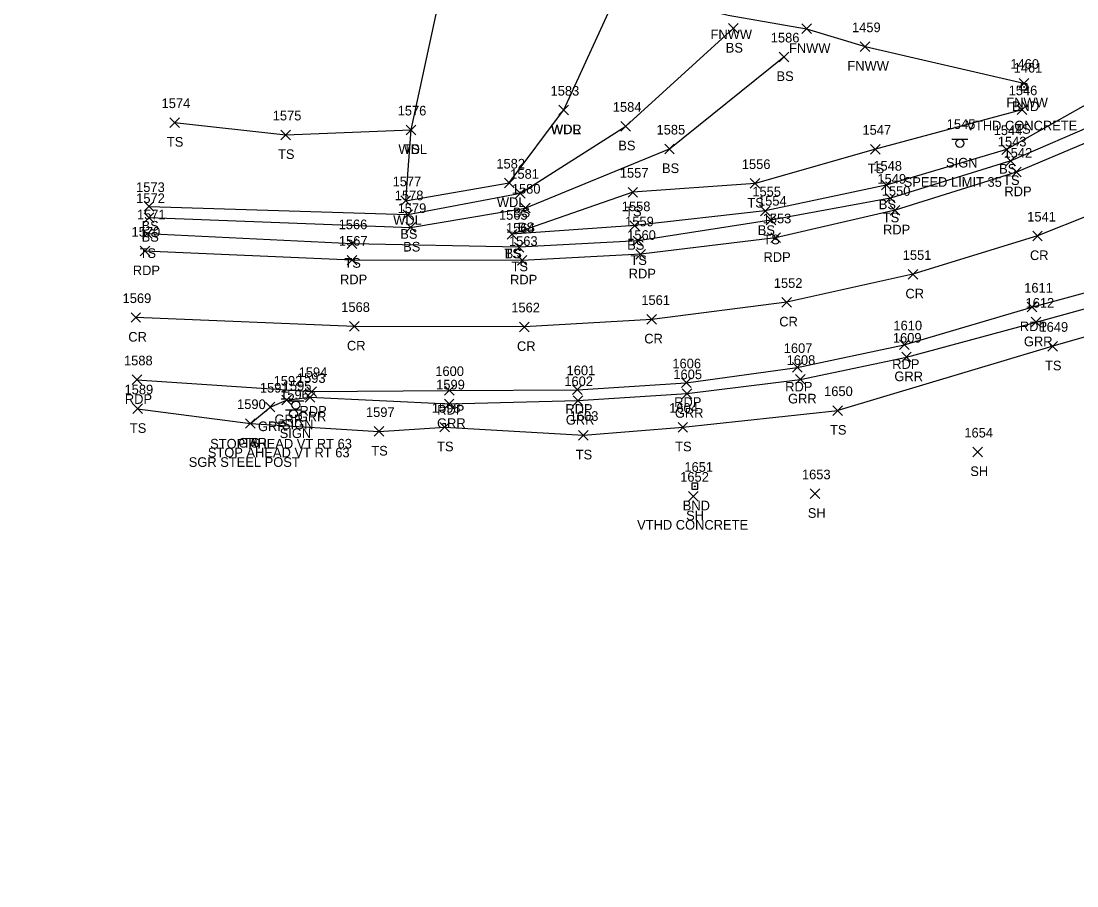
# Model space of a CAD drawing. Extents: x 1629176 to 1637209, y 606063 to 610167.
# Drawn here: x 1629563.1 to 1629782.2, y 606671.7 to 606851.1 of the extents above; entities that cross this region are included whole.
import ezdxf

# ---------------------------------------------------------------- set-up
doc = ezdxf.new("R2010")
doc.units = 0
for name, color, linetype in [('L_A', 7, 'Continuous'), ('L_C', 7, 'Continuous'), ('L_I', 7, 'Continuous'), ('L_TIC', 7, 'Continuous'), ('LAWA', 7, 'Continuous'), ('LELB', 7, 'Continuous'), ('LFNC', 7, 'Continuous'), ('M_A', 7, 'Continuous'), ('M_C', 7, 'Continuous'), ('M_I', 7, 'Continuous'), ('MHBP', 7, 'Continuous'), ('P_A', 7, 'Continuous'), ('P_I', 7, 'Continuous'), ('P_TIC', 7, 'Continuous'), ('PET', 7, 'Continuous'), ('PRC', 7, 'Continuous'), ('R_A', 7, 'Continuous'), ('R_C', 7, 'Continuous'), ('R_I', 7, 'Continuous'), ('R_TIC', 7, 'Continuous'), ('RGR', 7, 'Continuous'), ('S_A', 7, 'Continuous'), ('S_C', 7, 'Continuous'), ('S_I', 7, 'Continuous'), ('SSGN', 7, 'Continuous')]:
    doc.layers.add(name, color=color, linetype=linetype)

msp = doc.modelspace()

# ---------------------------------------------------------------- linework, layer by layer
at = {"layer": 'L_TIC'}
for points in [[(1629709.9, 606848.62), (1629711.9, 606850.62)], [(1629711.9, 606848.62), (1629709.9, 606850.62)], [(1629725.11, 606848.55), (1629727.11, 606850.55)], [(1629727.11, 606848.55), (1629725.11, 606850.55)], [(1629737.25, 606844.85), (1629739.25, 606846.85)], [(1629739.25, 606844.85), (1629737.25, 606846.85)], [(1629720.42, 606842.72), (1629722.42, 606844.72)], [(1629722.42, 606842.72), (1629720.42, 606844.72)], [(1629770.23, 606837.25), (1629772.23, 606839.25)], [(1629772.23, 606837.25), (1629770.23, 606839.25)], [(1629674.67, 606831.68), (1629676.67, 606833.68)], [(1629676.67, 606831.68), (1629674.67, 606833.68)], [(1629674.67, 606831.68), (1629676.67, 606833.68)], [(1629676.67, 606831.68), (1629674.67, 606833.68)], [(1629769.8, 606831.77), (1629771.8, 606833.77)], [(1629771.8, 606831.77), (1629769.8, 606833.77)], [(1629593.93, 606829.1), (1629595.93, 606831.1)], [(1629595.93, 606829.1), (1629593.93, 606831.1)], [(1629617, 606826.54), (1629619, 606828.54)], [(1629619, 606826.54), (1629617, 606828.54)], [(1629642.99, 606827.57), (1629644.99, 606829.57)], [(1629644.99, 606827.57), (1629642.99, 606829.57)], [(1629642.99, 606827.57), (1629644.99, 606829.57)], [(1629644.99, 606827.57), (1629642.99, 606829.57)], [(1629687.59, 606828.33), (1629689.59, 606830.33)], [(1629689.59, 606828.33), (1629687.59, 606830.33)], [(1629696.66, 606823.62), (1629698.66, 606825.62)], [(1629698.66, 606823.62), (1629696.66, 606825.62)], [(1629739.4, 606823.57), (1629741.4, 606825.57)], [(1629741.4, 606823.57), (1629739.4, 606825.57)], [(1629766.63, 606823.5), (1629768.63, 606825.5)], [(1629768.63, 606823.5), (1629766.63, 606825.5)], [(1629767.49, 606821.14), (1629769.49, 606823.14)], [(1629769.49, 606821.14), (1629767.49, 606823.14)], [(1629663.41, 606816.56), (1629665.41, 606818.56)], [(1629665.41, 606816.56), (1629663.41, 606818.56)], [(1629714.41, 606816.46), (1629716.41, 606818.46)], [(1629716.41, 606816.46), (1629714.41, 606818.46)], [(1629741.65, 606816.12), (1629743.65, 606818.12)], [(1629743.65, 606816.12), (1629741.65, 606818.12)], [(1629665.73, 606814.44), (1629667.73, 606816.44)], [(1629667.73, 606814.44), (1629665.73, 606816.44)], [(1629689.05, 606814.65), (1629691.05, 606816.65)], [(1629691.05, 606814.65), (1629689.05, 606816.65)], [(1629742.52, 606813.41), (1629744.52, 606815.41)], [(1629744.52, 606813.41), (1629742.52, 606815.41)], [(1629588.64, 606811.69), (1629590.64, 606813.69)], [(1629590.64, 606811.69), (1629588.64, 606813.69)], [(1629641.89, 606812.88), (1629643.89, 606814.88)], [(1629643.89, 606812.88), (1629641.89, 606814.88)], [(1629666.72, 606811.35), (1629668.72, 606813.35)], [(1629668.72, 606811.35), (1629666.72, 606813.35)], [(1629588.66, 606809.39), (1629590.66, 606811.39)], [(1629590.66, 606809.39), (1629588.66, 606811.39)], [(1629642.34, 606809.99), (1629644.34, 606811.99)], [(1629644.34, 606809.99), (1629642.34, 606811.99)], [(1629716.54, 606810.78), (1629718.54, 606812.78)], [(1629718.54, 606810.78), (1629716.54, 606812.78)], [(1629642.93, 606807.34), (1629644.93, 606809.34)], [(1629644.93, 606807.34), (1629642.93, 606809.34)], [(1629689.44, 606807.71), (1629691.44, 606809.71)], [(1629691.44, 606807.71), (1629689.44, 606809.71)], [(1629717.72, 606808.85), (1629719.72, 606810.85)], [(1629719.72, 606808.85), (1629717.72, 606810.85)], [(1629588.26, 606806.01), (1629590.26, 606808.01)], [(1629590.26, 606806.01), (1629588.26, 606808.01)], [(1629664, 606805.93), (1629666, 606807.93)], [(1629666, 606805.93), (1629664, 606807.93)], [(1629664, 606805.93), (1629666, 606807.93)], [(1629666, 606805.93), (1629664, 606807.93)], [(1629690.15, 606804.56), (1629692.15, 606806.56)], [(1629692.15, 606804.56), (1629690.15, 606806.56)], [(1629630.78, 606803.97), (1629632.78, 606805.97)], [(1629632.78, 606803.97), (1629630.78, 606805.97)], [(1629665.46, 606803.24), (1629667.46, 606805.24)], [(1629667.46, 606803.24), (1629665.46, 606805.24)], [(1629776.19, 606782.69), (1629778.19, 606784.69)], [(1629778.19, 606782.69), (1629776.19, 606784.69)], [(1629586.25, 606769.71), (1629588.25, 606771.71)], [(1629588.25, 606769.71), (1629586.25, 606771.71)], [(1629731.57, 606769.35), (1629733.57, 606771.35)], [(1629733.57, 606769.35), (1629731.57, 606771.35)], [(1629731.57, 606769.35), (1629733.57, 606771.35)], [(1629733.57, 606769.35), (1629731.57, 606771.35)], [(1629609.69, 606766.66), (1629611.69, 606768.66)], [(1629611.69, 606766.66), (1629609.69, 606768.66)], [(1629650.02, 606765.9), (1629652.02, 606767.9)], [(1629652.02, 606765.9), (1629650.02, 606767.9)], [(1629699.43, 606765.89), (1629701.43, 606767.89)], [(1629701.43, 606765.89), (1629699.43, 606767.89)], [(1629636.36, 606765.01), (1629638.36, 606767.01)], [(1629638.36, 606765.01), (1629636.36, 606767.01)], [(1629678.78, 606764.21), (1629680.78, 606766.21)], [(1629680.78, 606764.21), (1629678.78, 606766.21)], [(1629760.6, 606760.76), (1629762.6, 606762.76)], [(1629762.6, 606760.76), (1629760.6, 606762.76)], [(1629726.89, 606752.09), (1629728.89, 606754.09)], [(1629728.89, 606752.09), (1629726.89, 606754.09)], [(1629701.62, 606751.58), (1629703.62, 606753.58)], [(1629703.62, 606751.58), (1629701.62, 606753.58)]]:
    msp.add_lwpolyline(points, dxfattribs=at)
at = {"layer": 'LAWA'}
for points in [[(1629651.99, 606865.79), (1629643.99, 606828.57), (1629642.89, 606813.88), (1629664.41, 606817.56), (1629675.67, 606832.68)], [(1629687.21, 606857.94), (1629675.67, 606832.68)]]:
    msp.add_lwpolyline(points, dxfattribs=at)
at = {"layer": 'LELB'}
for points in [[(1629537.12, 607012.67), (1629575, 607007.04), (1629623.31, 606998.78), (1629670.49, 606990.16), (1629714.53, 606981.27), (1629760, 606971.03), (1629801.55, 606961.38), (1629838.05, 606950.95), (1629877.99, 606935.18), (1629884.4, 606927.34), (1629887.99, 606913), (1629884.23, 606901.72), (1629876.6, 606890.52), (1629858.53, 606872.94), (1629837.71, 606857.41), (1629816.19, 606845.34), (1629787.36, 606830.32), (1629768.49, 606822.14), (1629743.52, 606814.41), (1629718.72, 606809.85), (1629691.15, 606805.56), (1629666.46, 606804.24), (1629631.78, 606804.97), (1629589.26, 606807.01)], [(1629877.25, 606930.15), (1629884.92, 606913), (1629880.28, 606898.59), (1629867.99, 606890.41), (1629855.23, 606876.92), (1629834.43, 606863.57), (1629813.18, 606849.89), (1629785.68, 606834.66), (1629767.63, 606824.5), (1629742.65, 606817.12), (1629717.54, 606811.78), (1629690.44, 606808.71), (1629665, 606806.93)], [(1629589.64, 606812.69), (1629643.34, 606810.99), (1629666.73, 606815.44), (1629688.59, 606829.33), (1629710.9, 606849.62)], [(1629589.66, 606810.39), (1629643.93, 606808.34), (1629667.72, 606812.35), (1629697.66, 606824.62), (1629721.42, 606843.72)], [(1629770.8, 606832.77), (1629740.4, 606824.57), (1629715.41, 606817.46), (1629690.05, 606815.65), (1629665, 606806.93)], [(1629594.93, 606830.1), (1629618, 606827.54), (1629643.99, 606828.57)], [(1629974.23, 606671.73), (1629944.56, 606697.88), (1629917.84, 606720.26), (1629895.86, 606740.8), (1629872.45, 606761.2), (1629853.73, 606776.41), (1629836.55, 606788.97), (1629824.22, 606793.63), (1629808.76, 606792.78), (1629777.19, 606783.69), (1629732.57, 606770.35)], [(1629587.25, 606770.71), (1629610.69, 606767.66), (1629637.36, 606766.01), (1629651.02, 606766.9), (1629679.78, 606765.21), (1629700.43, 606766.89), (1629732.57, 606770.35)]]:
    msp.add_lwpolyline(points, dxfattribs=at)
at = {"layer": 'LFNC'}
msp.add_lwpolyline([(1629193.07, 606917.87), (1629225.59, 606916.68), (1629272.22, 606914.37), (1629291.9, 606913.28), (1629328.76, 606910.62), (1629372.75, 606906.84), (1629412.15, 606903.01), (1629459.35, 606897.68), (1629481.55, 606894.63), (1629529.36, 606888.4), (1629556.45, 606884.22), (1629596.1, 606877.05), (1629651.99, 606865.79), (1629687.21, 606857.94), (1629709.84, 606852.4), (1629726.11, 606849.55), (1629738.25, 606845.85), (1629771.23, 606838.25)], dxfattribs=at)
at = {"layer": 'MHBP'}
for p, q in [((1629771.91, 606838.13), (1629770.66, 606838.13)), ((1629770.66, 606838.13), (1629770.66, 606836.88)), ((1629771.91, 606838.13), (1629770.66, 606838.13)), ((1629770.66, 606838.13), (1629770.66, 606836.88)), ((1629771.91, 606836.88), (1629771.91, 606838.13)), ((1629771.91, 606836.88), (1629771.91, 606838.13)), ((1629770.66, 606836.88), (1629771.91, 606836.88)), ((1629770.66, 606836.88), (1629771.91, 606836.88)), ((1629703.57, 606755.3), (1629702.32, 606755.3)), ((1629702.32, 606755.3), (1629702.32, 606754.05)), ((1629703.57, 606755.3), (1629702.32, 606755.3)), ((1629702.32, 606755.3), (1629702.32, 606754.05)), ((1629702.32, 606754.05), (1629703.57, 606754.05)), ((1629702.32, 606754.05), (1629703.57, 606754.05)), ((1629703.57, 606754.05), (1629703.57, 606755.3)), ((1629703.57, 606754.05), (1629703.57, 606755.3))]:
    msp.add_line(p, q, dxfattribs=at)
for centre in [(1629771.26, 606837.47), (1629702.92, 606754.63)]:
    msp.add_circle(centre, 0.0833, dxfattribs=at)
at = {"layer": 'P_TIC'}
for points in [[(1629768.68, 606818.82), (1629770.68, 606820.82)], [(1629770.68, 606818.82), (1629768.68, 606820.82)], [(1629743.49, 606810.9), (1629745.49, 606812.9)], [(1629745.49, 606810.9), (1629743.49, 606812.9)], [(1629718.68, 606805.2), (1629720.68, 606807.2)], [(1629720.68, 606805.2), (1629718.68, 606807.2)], [(1629773.04, 606805.57), (1629775.04, 606807.57)], [(1629775.04, 606805.57), (1629773.04, 606807.57)], [(1629587.78, 606802.44), (1629589.78, 606804.44)], [(1629589.78, 606802.44), (1629587.78, 606804.44)], [(1629630.79, 606800.55), (1629632.79, 606802.55)], [(1629632.79, 606800.55), (1629630.79, 606802.55)], [(1629666.08, 606800.51), (1629668.08, 606802.51)], [(1629668.08, 606800.51), (1629666.08, 606802.51)], [(1629690.7, 606801.76), (1629692.7, 606803.76)], [(1629692.7, 606801.76), (1629690.7, 606803.76)], [(1629747.19, 606797.61), (1629749.19, 606799.61)], [(1629749.19, 606797.61), (1629747.19, 606799.61)], [(1629721.01, 606791.8), (1629723.01, 606793.8)], [(1629723.01, 606791.8), (1629721.01, 606793.8)], [(1629771.89, 606790.82), (1629773.89, 606792.82)], [(1629773.89, 606790.82), (1629771.89, 606792.82)], [(1629585.9, 606788.65), (1629587.9, 606790.65)], [(1629587.9, 606788.65), (1629585.9, 606790.65)], [(1629692.98, 606788.27), (1629694.98, 606790.27)], [(1629694.98, 606788.27), (1629692.98, 606790.27)], [(1629631.27, 606786.81), (1629633.27, 606788.81)], [(1629633.27, 606786.81), (1629631.27, 606788.81)], [(1629666.56, 606786.71), (1629668.56, 606788.71)], [(1629668.56, 606786.71), (1629666.56, 606788.71)], [(1629745.4, 606782.99), (1629747.4, 606784.99)], [(1629747.4, 606782.99), (1629745.4, 606784.99)], [(1629723.19, 606778.3), (1629725.19, 606780.3)], [(1629725.19, 606778.3), (1629723.19, 606780.3)], [(1629586.14, 606775.73), (1629588.14, 606777.73)], [(1629588.14, 606775.73), (1629586.14, 606777.73)], [(1629700.14, 606775.11), (1629702.14, 606777.11)], [(1629702.14, 606775.11), (1629700.14, 606777.11)], [(1629622.38, 606773.29), (1629624.38, 606775.29)], [(1629624.38, 606773.29), (1629622.38, 606775.29)], [(1629650.95, 606773.51), (1629652.95, 606775.51)], [(1629652.95, 606773.51), (1629650.95, 606775.51)], [(1629677.56, 606773.68), (1629679.56, 606775.68)], [(1629679.56, 606773.68), (1629677.56, 606775.68)]]:
    msp.add_lwpolyline(points, dxfattribs=at)
at = {"layer": 'PET'}
for points in [[(1629871.33, 606945.94), (1629880.42, 606941.23), (1629888.42, 606926.9), (1629889.97, 606912.21), (1629888.08, 606901.04), (1629880.59, 606887.29), (1629861.33, 606870.19), (1629839.75, 606855.53), (1629817.8, 606842.55), (1629788.82, 606827.89), (1629769.68, 606819.82), (1629744.49, 606811.9), (1629719.68, 606806.2), (1629691.7, 606802.76), (1629667.08, 606801.51), (1629631.79, 606801.55), (1629588.78, 606803.44)], [(1629587.14, 606776.73), (1629623.38, 606774.29), (1629651.95, 606774.51), (1629678.56, 606774.68), (1629701.14, 606776.11), (1629724.19, 606779.3), (1629746.4, 606783.99), (1629772.89, 606791.82), (1629808.22, 606801.42), (1629824.36, 606806.11), (1629835.79, 606810.93), (1629847.76, 606817.22), (1629860.47, 606825.17), (1629873.11, 606832.29), (1629887.14, 606850.82), (1629912.73, 606877.94), (1629938.57, 606904.89), (1629947.79, 606913.74), (1629954.28, 606917.5), (1629965.2, 606918.43)]]:
    msp.add_lwpolyline(points, dxfattribs=at)
at = {"layer": 'PRC'}
msp.add_lwpolyline([(1629930.37, 606928.51), (1629922.33, 606915.08), (1629903.69, 606892.32), (1629888.42, 606875.5), (1629871.3, 606859.39), (1629850.1, 606843.52), (1629825.75, 606829.77), (1629796.32, 606815.42), (1629774.04, 606806.57), (1629748.19, 606798.61), (1629722.01, 606792.8), (1629693.98, 606789.27), (1629667.56, 606787.71), (1629632.27, 606787.81), (1629586.9, 606789.65)], dxfattribs=at)
at = {"layer": 'R_TIC'}
for points in [[(1629772.74, 606787.69), (1629774.74, 606789.69)], [(1629774.74, 606787.69), (1629772.74, 606789.69)], [(1629745.85, 606780.44), (1629747.85, 606782.44)], [(1629747.85, 606780.44), (1629745.85, 606782.44)], [(1629723.79, 606775.82), (1629725.79, 606777.82)], [(1629725.79, 606775.82), (1629723.79, 606777.82)], [(1629622.02, 606772.09), (1629624.02, 606774.09)], [(1629624.02, 606772.09), (1629622.02, 606774.09)], [(1629700.28, 606772.86), (1629702.28, 606774.86)], [(1629702.28, 606772.86), (1629700.28, 606774.86)], [(1629613.78, 606770.08), (1629615.78, 606772.08)], [(1629615.78, 606770.08), (1629613.78, 606772.08)], [(1629617.2, 606771.52), (1629619.2, 606773.52)], [(1629619.2, 606771.52), (1629617.2, 606773.52)], [(1629650.93, 606770.73), (1629652.93, 606772.73)], [(1629652.93, 606770.73), (1629650.93, 606772.73)], [(1629677.65, 606771.42), (1629679.65, 606773.42)], [(1629679.65, 606771.42), (1629677.65, 606773.42)], [(1629609.69, 606766.66), (1629611.69, 606768.66)], [(1629611.69, 606766.66), (1629609.69, 606768.66)]]:
    msp.add_lwpolyline(points, dxfattribs=at)
at = {"layer": 'RGR'}
msp.add_lwpolyline([(1629610.69, 606767.66), (1629614.78, 606771.08), (1629618.2, 606772.52), (1629623.02, 606773.09), (1629651.93, 606771.73), (1629678.65, 606772.42), (1629701.28, 606773.86), (1629724.79, 606776.82), (1629746.85, 606781.44), (1629773.74, 606788.69), (1629807.56, 606798.03), (1629819.63, 606798.3), (1629831.2, 606794.55), (1629845.84, 606786.32), (1629881.37, 606757.13), (1629915.43, 606727.34), (1629943.21, 606703.31), (1629976.52, 606673.99)], dxfattribs=at)
at = {"layer": 'SSGN'}
for p, q in [((1629756.26, 606826.62), (1629759.6, 606826.62)), ((1629757.91, 606825.79), (1629757.91, 606825.79)), ((1629618.46, 606772.33), (1629621.79, 606772.33)), ((1629620.11, 606771.49), (1629620.11, 606771.49)), ((1629617.97, 606770.5), (1629621.31, 606770.5)), ((1629619.62, 606769.66), (1629619.62, 606769.66))]:
    msp.add_line(p, q, dxfattribs=at)
for centre in [(1629757.91, 606825.79), (1629620.11, 606771.49), (1629619.62, 606769.66)]:
    msp.add_circle(centre, 0.833, dxfattribs=at)

# ---------------------------------------------------------------- texts
at = {"layer": 'L_A'}
for s, p in [('FNWW', (1629706.18, 606847.4)), ('BS', (1629709.34, 606844.62)), ('FNWW', (1629722.46, 606844.55)), ('FNWW', (1629734.59, 606840.85)), ('BS', (1629719.87, 606838.72)), ('FNWW', (1629767.58, 606833.25)), ('WDR', (1629673.03, 606827.68)), ('WDL', (1629673.09, 606827.68)), ('TS', (1629769.21, 606827.77)), ('TS', (1629593.34, 606825.1)), ('BS', (1629687.03, 606824.33)), ('TS', (1629616.41, 606822.54)), ('WDL', (1629641.4, 606823.57)), ('TS', (1629642.4, 606823.57)), ('BS', (1629696.1, 606819.62)), ('TS', (1629738.81, 606819.57)), ('BS', (1629766.07, 606819.5)), ('TS', (1629766.9, 606817.14)), ('WDL', (1629661.83, 606812.56)), ('TS', (1629713.82, 606812.46)), ('BS', (1629741.09, 606812.12)), ('BS', (1629665.17, 606810.44)), ('TS', (1629688.46, 606810.65)), ('TS', (1629741.93, 606809.41)), ('BS', (1629588.09, 606807.69)), ('WDL', (1629640.31, 606808.88)), ('BS', (1629666.16, 606807.35)), ('BS', (1629715.98, 606806.78)), ('BS', (1629588.1, 606805.39)), ('BS', (1629641.78, 606805.99)), ('TS', (1629717.13, 606804.85)), ('BS', (1629642.38, 606803.34)), ('BS', (1629688.88, 606803.71)), ('TS', (1629587.67, 606802.01)), ('TS', (1629663.41, 606801.93)), ('BS', (1629663.45, 606801.93)), ('TS', (1629689.56, 606800.56)), ('TS', (1629630.19, 606799.97)), ('TS', (1629664.87, 606799.24)), ('TS', (1629775.6, 606778.69)), ('TS', (1629585.66, 606765.71)), ('TS', (1629730.98, 606765.35)), ('TS', (1629730.98, 606765.35)), ('TS', (1629609.1, 606762.66)), ('TS', (1629635.77, 606761.01)), ('TS', (1629649.43, 606761.9)), ('TS', (1629698.84, 606761.89)), ('TS', (1629678.19, 606760.21)), ('SH', (1629760.09, 606756.76)), ('SH', (1629701.11, 606747.58)), ('SH', (1629726.37, 606748.09))]:
    msp.add_text(s, height=2, dxfattribs=at).set_placement(p)
at = {"layer": 'L_C'}
msp.add_text('SGR STEEL POST', height=2, dxfattribs=at).set_placement((1629597.88, 606758.66))
at = {"layer": 'L_I'}
for s, p in [('1459', (1629735.54, 606848.85)), ('1586', (1629718.68, 606846.72)), ('1460', (1629768.41, 606841.25)), ('1583', (1629672.98, 606835.68)), ('1583', (1629672.98, 606835.68)), ('1546', (1629768.05, 606835.77)), ('1574', (1629592.24, 606833.1)), ('1576', (1629641.24, 606831.57)), ('1576', (1629641.24, 606831.57)), ('1584', (1629685.9, 606832.33)), ('1575', (1629615.31, 606830.54)), ('1585', (1629694.97, 606827.62)), ('1547', (1629737.71, 606827.57)), ('1544', (1629764.94, 606827.5)), ('1543', (1629765.8, 606825.14)), ('1582', (1629661.72, 606820.56)), ('1556', (1629712.67, 606820.46)), ('1548', (1629739.96, 606820.12)), ('1581', (1629664.61, 606818.44)), ('1557', (1629687.35, 606818.65)), ('1573', (1629586.95, 606815.69)), ('1577', (1629640.19, 606816.88)), ('1549', (1629740.82, 606817.41)), ('1572', (1629586.97, 606813.39)), ('1578', (1629640.64, 606813.99)), ('1580', (1629664.94, 606815.35)), ('1555', (1629714.85, 606814.78)), ('1579', (1629641.23, 606811.34)), ('1558', (1629687.75, 606811.71)), ('1554', (1629716.03, 606812.85)), ('1571', (1629587.13, 606810.01)), ('1565', (1629662.26, 606809.93)), ('1565', (1629662.26, 606809.93)), ('1566', (1629628.99, 606807.97)), ('1564', (1629663.72, 606807.24)), ('1559', (1629688.45, 606808.56)), ('1649', (1629774.45, 606786.69)), ('1589', (1629584.55, 606773.71)), ('1650', (1629729.75, 606773.35)), ('1650', (1629729.75, 606773.35)), ('1590', (1629607.91, 606770.66)), ('1598', (1629648.33, 606769.9)), ('1604', (1629697.61, 606769.89)), ('1597', (1629634.66, 606769.01)), ('1603', (1629676.96, 606768.21)), ('1654', (1629758.86, 606764.76)), ('1652', (1629699.88, 606755.58)), ('1653', (1629725.15, 606756.09))]:
    msp.add_text(s, height=2, dxfattribs=at).set_placement(p)
at = {"layer": 'M_A'}
for p in [(1629768.74, 606832.47), (1629700.41, 606749.64)]:
    msp.add_text('BND', height=2, dxfattribs=at).set_placement(p)
at = {"layer": 'M_C'}
for p in [(1629759.27, 606828.47), (1629690.94, 606745.64)]:
    msp.add_text('VTHD CONCRETE', height=2, dxfattribs=at).set_placement(p)
at = {"layer": 'M_I'}
for s, p in [('1461', (1629769.08, 606840.47)), ('1651', (1629700.75, 606757.64))]:
    msp.add_text(s, height=2, dxfattribs=at).set_placement(p)
at = {"layer": 'P_A'}
for s, p in [('RDP', (1629767.17, 606814.82)), ('RDP', (1629741.98, 606806.9)), ('RDP', (1629717.17, 606801.2)), ('CR', (1629772.47, 606801.57)), ('RDP', (1629586.27, 606798.44)), ('RDP', (1629629.28, 606796.55)), ('RDP', (1629664.57, 606796.51)), ('RDP', (1629689.19, 606797.76)), ('CR', (1629746.63, 606793.61)), ('CR', (1629720.44, 606787.8)), ('RDP', (1629770.38, 606786.82)), ('CR', (1629585.33, 606784.65)), ('CR', (1629630.71, 606782.81)), ('CR', (1629666, 606782.71)), ('CR', (1629692.42, 606784.27)), ('RDP', (1629743.89, 606778.99)), ('RDP', (1629721.68, 606774.3)), ('RDP', (1629584.62, 606771.73)), ('RDP', (1629649.44, 606769.51)), ('RDP', (1629676.04, 606769.68)), ('RDP', (1629698.63, 606771.11)), ('RDP', (1629620.87, 606769.29))]:
    msp.add_text(s, height=2, dxfattribs=at).set_placement(p)
at = {"layer": 'P_I'}
for s, p in [('1542', (1629766.99, 606822.82)), ('1550', (1629741.71, 606814.9)), ('1553', (1629716.99, 606809.2)), ('1541', (1629771.91, 606809.57)), ('1570', (1629586, 606806.44)), ('1567', (1629629.05, 606804.55)), ('1563', (1629664.34, 606804.51)), ('1560', (1629688.88, 606805.76)), ('1551', (1629746.07, 606801.61)), ('1552', (1629719.31, 606795.8)), ('1611', (1629771.28, 606794.82)), ('1569', (1629584.15, 606792.65)), ('1561', (1629691.81, 606792.27)), ('1568', (1629629.53, 606790.81)), ('1562', (1629664.82, 606790.71)), ('1610', (1629744.14, 606786.99)), ('1607', (1629721.37, 606782.3)), ('1588', (1629584.44, 606779.73)), ('1606', (1629698.26, 606779.11)), ('1594', (1629620.69, 606777.29)), ('1600', (1629649.05, 606777.51)), ('1601', (1629676.3, 606777.68))]:
    msp.add_text(s, height=2, dxfattribs=at).set_placement(p)
at = {"layer": 'R_A'}
for p in [(1629771.22, 606783.69), (1629744.34, 606776.44), (1629722.27, 606771.82), (1629615.68, 606767.52), (1629620.51, 606768.09), (1629676.14, 606767.42), (1629698.77, 606768.86), (1629612.26, 606766.08), (1629649.42, 606766.73), (1629608.18, 606762.66)]:
    msp.add_text('GRR', height=2, dxfattribs=at).set_placement(p)
at = {"layer": 'R_C'}
msp.add_text('SGR STEEL POST', height=2, dxfattribs=at).set_placement((1629597.88, 606758.66))
at = {"layer": 'R_I'}
for s, p in [('1612', (1629771.56, 606791.69)), ('1609', (1629744.02, 606784.44)), ('1608', (1629721.97, 606779.82)), ('1593', (1629620.33, 606776.09)), ('1605', (1629698.46, 606776.86)), ('1591', (1629612.65, 606774.08)), ('1592', (1629615.5, 606775.52)), ('1599', (1629649.23, 606774.73)), ('1602', (1629675.83, 606775.42)), ('1590', (1629607.91, 606770.66))]:
    msp.add_text(s, height=2, dxfattribs=at).set_placement(p)
at = {"layer": 'S_A'}
for p in [(1629755.05, 606820.77), (1629617.24, 606766.47), (1629616.76, 606764.64)]:
    msp.add_text('SIGN', height=2, dxfattribs=at).set_placement(p)
at = {"layer": 'S_C'}
for s, p in [('SPEED LIMIT 35', (1629746.27, 606816.77)), ('STOP AHEAD VT RT 63', (1629602.32, 606762.47)), ('STOP AHEAD VT RT 63', (1629601.84, 606760.64))]:
    msp.add_text(s, height=2, dxfattribs=at).set_placement(p)
at = {"layer": 'S_I'}
for s, p in [('1545', (1629755.2, 606828.77)), ('1595', (1629617.39, 606774.47)), ('1596', (1629616.85, 606772.64))]:
    msp.add_text(s, height=2, dxfattribs=at).set_placement(p)

doc.saveas('drawing.dxf')
